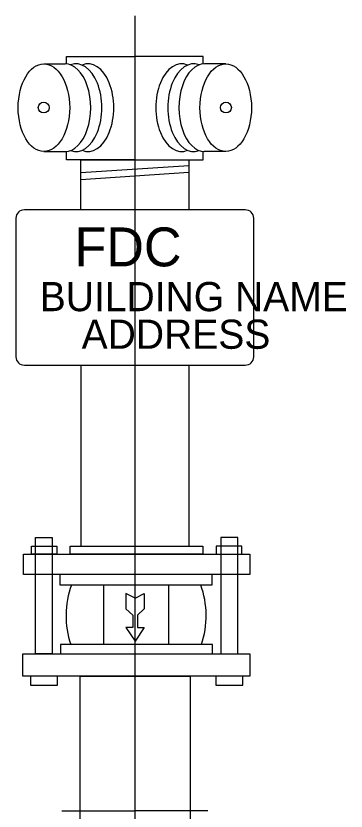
# Model space of a CAD drawing. Extents: x -121875 to -117742, y -103854 to -101122.
# Drawn here: x -118274.3 to -118235.2, y -101493.5 to -101399.2 of the extents above; entities that cross this region are included whole.
import ezdxf

# ---------------------------------------------------------------- set-up
doc = ezdxf.new("R2010")
doc.units = 0
doc.layers.add('22', color=7, linetype='Continuous')

msp = doc.modelspace()

# ---------------------------------------------------------------- linework, layer by layer
at = {"layer": '22'}
for p, q in [((-118260.219, -101399.159), (-118260.219, -101625.715)), ((-118270.999, -101404.847), (-118268.499, -101404.847)), ((-118249.439, -101404.847), (-118251.94, -101404.847)), ((-118270.999, -101415.256), (-118268.455, -101415.256)), ((-118249.439, -101415.256), (-118251.983, -101415.256)), ((-118266.618, -101417.736), (-118253.821, -101416.893)), ((-118266.618, -101418.565), (-118253.821, -101417.722)), ((-118266.618, -101440.608), (-118266.618, -101462.078)), ((-118253.821, -101440.608), (-118253.821, -101462.078)), ((-118268.876, -101493.516), (-118260.219, -101493.516)), ((-118251.562, -101493.516), (-118260.219, -101493.516))]:
    msp.add_line(p, q, dxfattribs=at)
for points in [[(-118268.321, -101404.855), (-118268.321, -101403.963), (-118260.219, -101403.963)], [(-118252.118, -101404.847), (-118252.118, -101403.963), (-118260.219, -101403.963)], [(-118260.219, -101416.239), (-118268.321, -101416.239), (-118268.321, -101415.247)], [(-118260.219, -101416.239), (-118252.118, -101416.239), (-118252.118, -101415.256)], [(-118247.118, -101422.174), (-118273.321, -101422.174)], [(-118274.321, -101423.174), (-118274.321, -101439.608)], [(-118246.118, -101439.608), (-118246.118, -101423.174)], [(-118273.321, -101440.608), (-118247.118, -101440.608)], [(-118260.197, -101468.264), (-118261.302, -101467.697), (-118261.302, -101469.529), (-118260.474, -101470.281), (-118260.474, -101471.724), (-118261.302, -101471.724), (-118260.197, -101473.381)], [(-118260.197, -101468.264), (-118259.092, -101467.697), (-118259.092, -101469.529), (-118259.921, -101470.281), (-118259.921, -101471.724), (-118259.092, -101471.724), (-118260.197, -101473.381)]]:
    msp.add_lwpolyline(points, dxfattribs=at)
for points in [[(-118266.618, -101416.239), (-118253.821, -101416.239), (-118253.821, -101422.174), (-118266.618, -101422.174)], [(-118272.009, -101461.061), (-118270.003, -101461.061), (-118270.003, -101474.886), (-118272.009, -101474.886)], [(-118248.007, -101461.061), (-118250.014, -101461.061), (-118250.014, -101474.886), (-118248.007, -101474.886)], [(-118272.489, -101462.078), (-118269.451, -101462.078), (-118269.451, -101463.052), (-118272.489, -101463.052)], [(-118267.873, -101462.078), (-118252.143, -101462.078), (-118252.143, -101463.052), (-118267.873, -101463.052)], [(-118247.528, -101462.078), (-118250.566, -101462.078), (-118250.566, -101463.052), (-118247.528, -101463.052)], [(-118273.434, -101463.052), (-118246.583, -101463.052), (-118246.583, -101465.451), (-118273.434, -101465.451)], [(-118251.039, -101465.451), (-118269.094, -101465.451), (-118269.094, -101466.679), (-118251.039, -101466.679)], [(-118263.904, -101466.679), (-118256.229, -101466.679), (-118256.229, -101473.774), (-118263.904, -101473.774)], [(-118250.995, -101473.774), (-118269.051, -101473.774), (-118269.051, -101474.886), (-118250.995, -101474.886)], [(-118273.492, -101474.886), (-118246.568, -101474.886), (-118246.568, -101477.503), (-118273.492, -101477.503)], [(-118272.605, -101478.579), (-118269.407, -101478.579), (-118269.407, -101477.503), (-118272.605, -101477.503)], [(-118266.688, -101477.503), (-118253.648, -101477.503), (-118253.648, -101565.674), (-118266.688, -101565.674)], [(-118250.61, -101478.579), (-118247.411, -101478.579), (-118247.411, -101477.503), (-118250.61, -101477.503)]]:
    msp.add_lwpolyline(points, close=True, dxfattribs=at)
for centre in [(-118271.025, -101410.04), (-118249.414, -101410.04)]:
    msp.add_circle(centre, 0.64, dxfattribs=at)
for centre, radius, start, end in [((-118273.321, -101423.174), 1, 90, 180), ((-118247.118, -101423.174), 1, 0, 90), ((-118273.321, -101439.608), 1, 180, 270), ((-118247.118, -101439.608), 1, 270, 0), ((-118257.6, -101470.352), 10.773, 160.07026, 198.5209), ((-118262.533, -101470.352), 10.773, 341.4791, 19.92974)]:
    msp.add_arc(centre, radius, start, end, dxfattribs=at)
for centre, start_param, end_param in [((-118265.766, -101410.051), 2.906088, 6.51869), ((-118254.673, -101410.051), 6.047681, 9.660282), ((-118268.499, -101410.051), 3.141591, 6.283187), ((-118267.19, -101410.051), 2.925632, 6.499146), ((-118253.248, -101410.051), 6.067225, 9.640738), ((-118251.94, -101410.051), 6.283184, 9.424779)]:
    msp.add_ellipse(centre, major_axis=(0, 5.205), ratio=0.586592, start_param=start_param, end_param=end_param, dxfattribs=at)
for centre in [(-118270.999, -101410.051), (-118249.439, -101410.051)]:
    msp.add_ellipse(centre, major_axis=(0, 5.205), ratio=0.586592, dxfattribs=at)

# ---------------------------------------------------------------- texts
for s, height, p in [('FDC', 4.6179, (-118267.369, -101428.882)), ('BUILDING NAME', 3.46224, (-118271.497, -101434.202)), ('ADDRESS', 3.4622, (-118266.527, -101438.665))]:
    msp.add_text(s, height=height, dxfattribs=at).set_placement(p)

doc.saveas('drawing.dxf')
